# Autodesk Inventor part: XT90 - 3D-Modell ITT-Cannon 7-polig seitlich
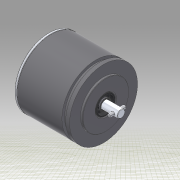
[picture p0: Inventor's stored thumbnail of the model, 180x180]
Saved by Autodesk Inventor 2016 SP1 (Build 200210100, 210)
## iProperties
Category: Winkelsensor
Company: IBS-Hühne GmbH
Created: 2016-03
Part Number: XT90 - 3D-Modell ITT-Cannon 7-polig seitlich
Project: XT90 A
User Status: Produktion
Material: AlMgSi1, schwarz eloxiert
Description: XT00000105
Vendor: IBS-Hühne GmbH
Document SubType Name: Modeling
Mfg Approved By: Welke
Designer: Geisbauer
Engineer: ---
Mass: 1186.34 g
Surface Area: 412.877 cm^2
Volume: 439.384 cm^3
Density: 2.7 g/cm^3
Appearance: Aluminum (schwarz eloxiert)
Title: 3D-Modell
Subject: XT90 A
Comments: IBS-Hühne GmbH Industriestraße 29 76287 Rheinstetten info@ibs-huehne.de
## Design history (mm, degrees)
node "3D-Modell XTB90 A mit Stecker ITT-Cannon 7-polig seitlich" dims "d0" = 10
feature "Volumenkörper1::3D-Modell XTB90 A mit Stecker ITT-Cannon 7-p" dims "d0" = 10
tag "Bezeichnung1"
node "Volumenkörper1"
